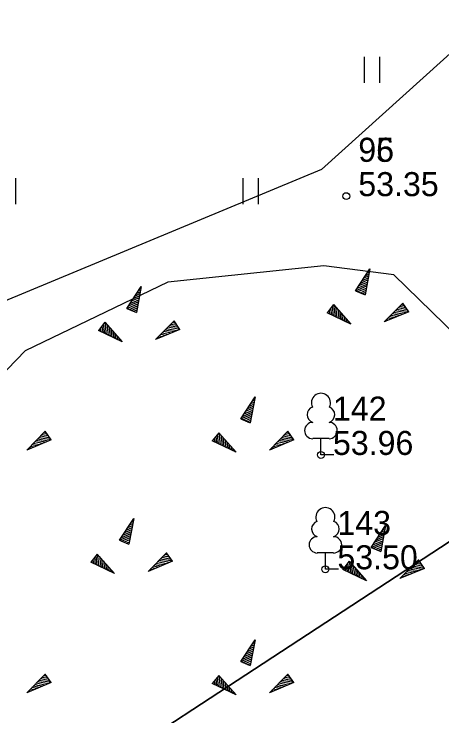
# Model space of a CAD drawing. Extents: x 538599 to 541973, y 6559689 to 6564516.
# Drawn here: x 540570.55 to 540583.02, y 6561313.83 to 6561334.28 of the extents above; entities that cross this region are included whole.
import ezdxf

# ---------------------------------------------------------------- set-up
doc = ezdxf.new("R2010")
doc.units = 0
for name, color, linetype in [('HALJASTUS', 7, 'Continuous'), ('KORGUS-EH2000', 7, 'Continuous'), ('MOOTKORG-EH2000', 7, 'Continuous'), ('MOOTMPUNKT', 7, 'Continuous'), ('MOOTNR', 7, 'Continuous'), ('MOOTPIIR', 7, 'Continuous'), ('PIIR', 7, 'Continuous'), ('PUU', 7, 'Continuous'), ('RELJEEF', 7, 'Continuous')]:
    doc.layers.add(name, color=color, linetype=linetype)

msp = doc.modelspace()

# ---------------------------------------------------------------- linework, layer by layer
at = {"layer": 'HALJASTUS'}
for p, q in [((540580.747, 6561333.033), (540580.747, 6561332.272)), ((540581.202, 6561333.033), (540581.202, 6561332.272)), ((540570.596, 6561329.498), (540570.596, 6561328.737)), ((540577.212, 6561329.498), (540577.212, 6561328.737)), ((540577.667, 6561329.498), (540577.667, 6561328.737))]:
    msp.add_line(p, q, dxfattribs=at)
at = {"layer": 'KORGUS-EH2000'}
msp.add_circle((540580.231, 6561328.973), 0.1, dxfattribs=at)
at = {"layer": 'MOOTMPUNKT'}
for centre in [(540580.231, 6561328.973), (540579.492, 6561321.433), (540579.622, 6561318.102)]:
    msp.add_circle(centre, 0.1, dxfattribs=at)
at = {"layer": 'MOOTPIIR'}
msp.add_lwpolyline([(540611.814, 6561347.628), (540600.551, 6561344.045), (540588.991, 6561338.307), (540579.507, 6561329.749), (540567.369, 6561324.711), (540557.296, 6561315.504), (540537.549, 6561303.29), (540525.23, 6561316.048), (540500.22, 6561345.282), (540476.488, 6561371.995), (540449.028, 6561405.277), (540428.792, 6561428.292), (540413.022, 6561448.218), (540405.096, 6561459.889), (540393.809, 6561473.145)], dxfattribs=at)
at = {"layer": 'PIIR'}
for points in [[(540501.31, 6561330.86), (540569.6, 6561385.93), (540606.26, 6561333.96), (540535.92, 6561287.97)], [(540535.92, 6561287.97), (540606.26, 6561333.96), (540640.63, 6561283.66), (540573.77, 6561238.75)]]:
    msp.add_lwpolyline(points, close=True, dxfattribs=at)
at = {"layer": 'PUU'}
for p, q in [((540579.732, 6561321.908), (540579.252, 6561321.908)), ((540579.492, 6561321.433), (540579.492, 6561321.908)), ((540579.872, 6561321.433), (540579.492, 6561321.433)), ((540579.862, 6561318.577), (540579.382, 6561318.577)), ((540579.622, 6561318.102), (540579.622, 6561318.577)), ((540580.002, 6561318.102), (540579.622, 6561318.102))]:
    msp.add_line(p, q, dxfattribs=at)
for centre, radius, start, end in [((540579.492, 6561322.953), 0.277, 332.5799, 207.4201), ((540579.322, 6561322.606), 0.233, 109.0217, 253.1415), ((540579.662, 6561322.606), 0.233, 286.8508, 70.9859), ((540579.255, 6561322.145), 0.238, 90.0016, 269.3953), ((540579.729, 6561322.145), 0.238, 270.6047, 89.9984), ((540579.622, 6561319.622), 0.277, 332.5799, 207.4201), ((540579.452, 6561319.275), 0.233, 109.0217, 253.1415), ((540579.792, 6561319.275), 0.233, 286.8508, 70.9859), ((540579.385, 6561318.814), 0.238, 90.0016, 269.3953), ((540579.859, 6561318.814), 0.238, 270.6047, 89.9984)]:
    msp.add_arc(centre, radius, start, end, dxfattribs=at)
at = {"layer": 'RELJEEF'}
for p, q in [((540580.501, 6561326.216), (540580.921, 6561326.856)), ((540580.921, 6561326.856), (540580.781, 6561326.101)), ((540580.896, 6561326.816), (540580.916, 6561326.826)), ((540580.701, 6561326.516), (540580.871, 6561326.591)), ((540580.751, 6561326.591), (540580.881, 6561326.651)), ((540580.796, 6561326.666), (540580.896, 6561326.706)), ((540580.846, 6561326.741), (540580.906, 6561326.766)), ((540580.551, 6561326.291), (540580.836, 6561326.411)), ((540580.601, 6561326.366), (540580.851, 6561326.471)), ((540580.651, 6561326.441), (540580.776, 6561326.496)), ((540580.776, 6561326.496), (540580.861, 6561326.531)), ((540573.835, 6561325.698), (540574.255, 6561326.338)), ((540574.255, 6561326.338), (540574.115, 6561325.583)), ((540574.13, 6561326.148), (540574.23, 6561326.188)), ((540574.18, 6561326.223), (540574.24, 6561326.248)), ((540574.23, 6561326.298), (540574.25, 6561326.308)), ((540580.501, 6561326.216), (540580.826, 6561326.356)), ((540580.501, 6561326.216), (540580.781, 6561326.101)), ((540580.566, 6561326.191), (540580.816, 6561326.296)), ((540580.631, 6561326.161), (540580.806, 6561326.236)), ((540580.701, 6561326.136), (540580.796, 6561326.176)), ((540573.935, 6561325.848), (540574.185, 6561325.953)), ((540573.985, 6561325.923), (540574.11, 6561325.978)), ((540574.035, 6561325.998), (540574.205, 6561326.073)), ((540574.085, 6561326.073), (540574.215, 6561326.133)), ((540574.11, 6561325.978), (540574.195, 6561326.013)), ((540580.766, 6561326.111), (540580.781, 6561326.116)), ((540573.835, 6561325.698), (540574.16, 6561325.838)), ((540573.885, 6561325.773), (540574.17, 6561325.893)), ((540573.9, 6561325.673), (540574.15, 6561325.778)), ((540579.86, 6561325.815), (540579.675, 6561325.575)), ((540579.815, 6561325.76), (540579.85, 6561325.49)), ((540579.86, 6561325.815), (540580.365, 6561325.245)), ((540579.86, 6561325.815), (540579.905, 6561325.465)), ((540579.92, 6561325.75), (540579.96, 6561325.44)), ((540581.339, 6561325.31), (540581.879, 6561325.855)), ((540581.969, 6561325.72), (540581.784, 6561325.755)), ((540581.929, 6561325.78), (540581.829, 6561325.8)), ((540581.889, 6561325.84), (540581.869, 6561325.84)), ((540582.049, 6561325.605), (540581.879, 6561325.855)), ((540573.835, 6561325.698), (540574.115, 6561325.583)), ((540573.965, 6561325.643), (540574.14, 6561325.718)), ((540574.035, 6561325.618), (540574.13, 6561325.658)), ((540574.1, 6561325.593), (540574.115, 6561325.598)), ((540580.365, 6561325.245), (540579.675, 6561325.575)), ((540579.685, 6561325.59), (540579.69, 6561325.57)), ((540579.73, 6561325.645), (540579.745, 6561325.545)), ((540579.775, 6561325.705), (540579.8, 6561325.52)), ((540579.98, 6561325.68), (540580.015, 6561325.415)), ((540580.04, 6561325.615), (540580.055, 6561325.475)), ((540580.095, 6561325.545), (540580.125, 6561325.36)), ((540582.049, 6561325.605), (540581.339, 6561325.31)), ((540581.664, 6561325.525), (540581.574, 6561325.545)), ((540581.879, 6561325.535), (540581.614, 6561325.585)), ((540581.964, 6561325.57), (540581.659, 6561325.63)), ((540582.049, 6561325.605), (540581.699, 6561325.67)), ((540582.009, 6561325.66), (540581.744, 6561325.715)), ((540574.672, 6561324.792), (540575.212, 6561325.337)), ((540575.382, 6561325.087), (540575.212, 6561325.337)), ((540580.055, 6561325.475), (540580.07, 6561325.385)), ((540580.155, 6561325.48), (540580.175, 6561325.335)), ((540580.215, 6561325.41), (540580.23, 6561325.31)), ((540580.275, 6561325.345), (540580.285, 6561325.28)), ((540581.464, 6561325.36), (540581.404, 6561325.375)), ((540581.549, 6561325.395), (540581.444, 6561325.415)), ((540581.629, 6561325.43), (540581.489, 6561325.46)), ((540581.714, 6561325.465), (540581.529, 6561325.5)), ((540581.799, 6561325.5), (540581.664, 6561325.525)), ((540573.193, 6561325.297), (540573.008, 6561325.057)), ((540573.108, 6561325.187), (540573.133, 6561325.002)), ((540573.148, 6561325.242), (540573.183, 6561324.972)), ((540573.193, 6561325.297), (540573.698, 6561324.727)), ((540573.193, 6561325.297), (540573.238, 6561324.947)), ((540573.253, 6561325.232), (540573.293, 6561324.922)), ((540573.313, 6561325.162), (540573.348, 6561324.897)), ((540575.382, 6561325.087), (540575.032, 6561325.152)), ((540575.342, 6561325.142), (540575.077, 6561325.197)), ((540575.302, 6561325.202), (540575.117, 6561325.237)), ((540575.262, 6561325.262), (540575.162, 6561325.282)), ((540575.222, 6561325.322), (540575.202, 6561325.322)), ((540580.335, 6561325.275), (540580.34, 6561325.255)), ((540581.379, 6561325.325), (540581.364, 6561325.33)), ((540573.698, 6561324.727), (540573.008, 6561325.057)), ((540573.018, 6561325.072), (540573.023, 6561325.052)), ((540573.063, 6561325.127), (540573.078, 6561325.027)), ((540573.373, 6561325.097), (540573.388, 6561324.957)), ((540573.388, 6561324.957), (540573.403, 6561324.867)), ((540573.428, 6561325.027), (540573.458, 6561324.842)), ((540573.488, 6561324.962), (540573.508, 6561324.817)), ((540575.382, 6561325.087), (540574.672, 6561324.792)), ((540574.962, 6561324.912), (540574.822, 6561324.942)), ((540575.047, 6561324.947), (540574.862, 6561324.982)), ((540574.997, 6561325.007), (540574.907, 6561325.027)), ((540575.212, 6561325.017), (540574.947, 6561325.067)), ((540575.297, 6561325.052), (540574.992, 6561325.112)), ((540575.132, 6561324.982), (540574.997, 6561325.007)), ((540573.548, 6561324.892), (540573.563, 6561324.792)), ((540573.608, 6561324.827), (540573.618, 6561324.762)), ((540573.668, 6561324.757), (540573.673, 6561324.737)), ((540574.712, 6561324.807), (540574.697, 6561324.812)), ((540574.797, 6561324.842), (540574.737, 6561324.857)), ((540574.882, 6561324.877), (540574.777, 6561324.897)), ((540577.153, 6561322.482), (540577.573, 6561323.122)), ((540577.573, 6561323.122), (540577.433, 6561322.367)), ((540577.548, 6561323.082), (540577.568, 6561323.092)), ((540577.403, 6561322.857), (540577.533, 6561322.917)), ((540577.448, 6561322.932), (540577.548, 6561322.972)), ((540577.498, 6561323.007), (540577.558, 6561323.032)), ((540577.203, 6561322.557), (540577.488, 6561322.677)), ((540577.253, 6561322.632), (540577.503, 6561322.737)), ((540577.303, 6561322.707), (540577.428, 6561322.762)), ((540577.353, 6561322.782), (540577.523, 6561322.857)), ((540577.428, 6561322.762), (540577.513, 6561322.797)), ((540577.153, 6561322.482), (540577.478, 6561322.622)), ((540577.153, 6561322.482), (540577.433, 6561322.367)), ((540577.218, 6561322.457), (540577.468, 6561322.562)), ((540577.283, 6561322.427), (540577.458, 6561322.502)), ((540577.353, 6561322.402), (540577.448, 6561322.442)), ((540577.418, 6561322.377), (540577.433, 6561322.382)), ((540570.92, 6561321.576), (540571.46, 6561322.121)), ((540571.51, 6561322.046), (540571.41, 6561322.066)), ((540571.47, 6561322.106), (540571.45, 6561322.106)), ((540571.63, 6561321.871), (540571.46, 6561322.121)), ((540576.512, 6561322.081), (540576.327, 6561321.841)), ((540576.512, 6561322.081), (540577.017, 6561321.511)), ((540576.512, 6561322.081), (540576.557, 6561321.731)), ((540577.991, 6561321.576), (540578.531, 6561322.121)), ((540578.581, 6561322.046), (540578.481, 6561322.066)), ((540578.541, 6561322.106), (540578.521, 6561322.106)), ((540578.701, 6561321.871), (540578.531, 6561322.121)), ((540571.63, 6561321.871), (540570.92, 6561321.576)), ((540571.545, 6561321.836), (540571.24, 6561321.896)), ((540571.63, 6561321.871), (540571.28, 6561321.936)), ((540571.59, 6561321.926), (540571.325, 6561321.981)), ((540571.55, 6561321.986), (540571.365, 6561322.021)), ((540576.382, 6561321.911), (540576.397, 6561321.811)), ((540576.427, 6561321.971), (540576.452, 6561321.786)), ((540576.467, 6561322.026), (540576.502, 6561321.756)), ((540576.572, 6561322.016), (540576.612, 6561321.706)), ((540576.632, 6561321.946), (540576.667, 6561321.681)), ((540576.692, 6561321.881), (540576.707, 6561321.741)), ((540578.701, 6561321.871), (540577.991, 6561321.576)), ((540578.616, 6561321.836), (540578.311, 6561321.896)), ((540578.701, 6561321.871), (540578.351, 6561321.936)), ((540578.661, 6561321.926), (540578.396, 6561321.981)), ((540578.621, 6561321.986), (540578.436, 6561322.021)), ((540571.13, 6561321.661), (540571.025, 6561321.681)), ((540571.21, 6561321.696), (540571.07, 6561321.726)), ((540571.295, 6561321.731), (540571.11, 6561321.766)), ((540571.245, 6561321.791), (540571.155, 6561321.811)), ((540571.46, 6561321.801), (540571.195, 6561321.851)), ((540571.38, 6561321.766), (540571.245, 6561321.791)), ((540577.017, 6561321.511), (540576.327, 6561321.841)), ((540576.337, 6561321.856), (540576.342, 6561321.836)), ((540576.707, 6561321.741), (540576.722, 6561321.651)), ((540576.747, 6561321.811), (540576.777, 6561321.626)), ((540576.807, 6561321.746), (540576.827, 6561321.601)), ((540576.867, 6561321.676), (540576.882, 6561321.576)), ((540578.201, 6561321.661), (540578.096, 6561321.681)), ((540578.281, 6561321.696), (540578.141, 6561321.726)), ((540578.366, 6561321.731), (540578.181, 6561321.766)), ((540578.316, 6561321.791), (540578.226, 6561321.811)), ((540578.531, 6561321.801), (540578.266, 6561321.851)), ((540578.451, 6561321.766), (540578.316, 6561321.791)), ((540570.96, 6561321.591), (540570.945, 6561321.596)), ((540571.045, 6561321.626), (540570.985, 6561321.641)), ((540576.927, 6561321.611), (540576.937, 6561321.546)), ((540576.987, 6561321.541), (540576.992, 6561321.521)), ((540578.031, 6561321.591), (540578.016, 6561321.596)), ((540578.116, 6561321.626), (540578.056, 6561321.641)), ((540573.618, 6561318.946), (540574.038, 6561319.586)), ((540574.038, 6561319.586), (540573.898, 6561318.831)), ((540573.913, 6561319.396), (540574.013, 6561319.436)), ((540573.963, 6561319.471), (540574.023, 6561319.496)), ((540574.013, 6561319.546), (540574.033, 6561319.556)), ((540573.718, 6561319.096), (540573.968, 6561319.201)), ((540573.768, 6561319.171), (540573.893, 6561319.226)), ((540573.818, 6561319.246), (540573.988, 6561319.321)), ((540573.868, 6561319.321), (540573.998, 6561319.381)), ((540573.893, 6561319.226), (540573.978, 6561319.261)), ((540580.957, 6561318.739), (540581.377, 6561319.379)), ((540581.377, 6561319.379), (540581.237, 6561318.624)), ((540581.252, 6561319.189), (540581.352, 6561319.229)), ((540581.302, 6561319.264), (540581.362, 6561319.289)), ((540581.352, 6561319.339), (540581.372, 6561319.349)), ((540573.618, 6561318.946), (540573.943, 6561319.086)), ((540573.668, 6561319.021), (540573.953, 6561319.141)), ((540573.683, 6561318.921), (540573.933, 6561319.026)), ((540581.107, 6561318.964), (540581.232, 6561319.019)), ((540581.157, 6561319.039), (540581.327, 6561319.114)), ((540581.207, 6561319.114), (540581.337, 6561319.174)), ((540581.232, 6561319.019), (540581.317, 6561319.054)), ((540573.618, 6561318.946), (540573.898, 6561318.831)), ((540573.748, 6561318.891), (540573.923, 6561318.966)), ((540573.818, 6561318.866), (540573.913, 6561318.906)), ((540573.883, 6561318.841), (540573.898, 6561318.846)), ((540580.957, 6561318.739), (540581.282, 6561318.879)), ((540581.007, 6561318.814), (540581.292, 6561318.934)), ((540581.022, 6561318.714), (540581.272, 6561318.819)), ((540581.057, 6561318.889), (540581.307, 6561318.994)), ((540580.957, 6561318.739), (540581.237, 6561318.624)), ((540581.087, 6561318.684), (540581.262, 6561318.759)), ((540581.157, 6561318.659), (540581.252, 6561318.699)), ((540581.222, 6561318.634), (540581.237, 6561318.639)), ((540572.976, 6561318.545), (540572.791, 6561318.305)), ((540572.891, 6561318.435), (540572.916, 6561318.25)), ((540572.931, 6561318.49), (540572.966, 6561318.22)), ((540572.976, 6561318.545), (540573.481, 6561317.975)), ((540572.976, 6561318.545), (540573.021, 6561318.195)), ((540573.036, 6561318.48), (540573.076, 6561318.17)), ((540573.096, 6561318.41), (540573.131, 6561318.145)), ((540574.455, 6561318.04), (540574.995, 6561318.585)), ((540575.165, 6561318.335), (540574.815, 6561318.4)), ((540575.125, 6561318.39), (540574.86, 6561318.445)), ((540575.085, 6561318.45), (540574.9, 6561318.485)), ((540575.045, 6561318.51), (540574.945, 6561318.53)), ((540575.005, 6561318.57), (540574.985, 6561318.57)), ((540575.165, 6561318.335), (540574.995, 6561318.585)), ((540573.481, 6561317.975), (540572.791, 6561318.305)), ((540572.801, 6561318.32), (540572.806, 6561318.3)), ((540572.846, 6561318.375), (540572.861, 6561318.275)), ((540573.156, 6561318.345), (540573.171, 6561318.205)), ((540573.171, 6561318.205), (540573.186, 6561318.115)), ((540573.211, 6561318.275), (540573.241, 6561318.09)), ((540573.271, 6561318.21), (540573.291, 6561318.065)), ((540575.165, 6561318.335), (540574.455, 6561318.04)), ((540574.745, 6561318.16), (540574.605, 6561318.19)), ((540574.83, 6561318.195), (540574.645, 6561318.23)), ((540574.78, 6561318.255), (540574.69, 6561318.275)), ((540574.995, 6561318.265), (540574.73, 6561318.315)), ((540575.08, 6561318.3), (540574.775, 6561318.36)), ((540574.915, 6561318.23), (540574.78, 6561318.255)), ((540580.315, 6561318.338), (540580.13, 6561318.098)), ((540580.23, 6561318.228), (540580.255, 6561318.043)), ((540580.27, 6561318.283), (540580.305, 6561318.013)), ((540580.315, 6561318.338), (540580.82, 6561317.768)), ((540580.315, 6561318.338), (540580.36, 6561317.988)), ((540580.375, 6561318.273), (540580.415, 6561317.963)), ((540580.435, 6561318.203), (540580.47, 6561317.938)), ((540581.795, 6561317.833), (540582.335, 6561318.378)), ((540582.505, 6561318.128), (540582.155, 6561318.193)), ((540582.465, 6561318.183), (540582.2, 6561318.238)), ((540582.425, 6561318.243), (540582.24, 6561318.278)), ((540582.385, 6561318.303), (540582.285, 6561318.323)), ((540582.345, 6561318.363), (540582.325, 6561318.363)), ((540582.505, 6561318.128), (540582.335, 6561318.378)), ((540573.331, 6561318.14), (540573.346, 6561318.04)), ((540573.391, 6561318.075), (540573.401, 6561318.01)), ((540573.451, 6561318.005), (540573.456, 6561317.985)), ((540574.495, 6561318.055), (540574.48, 6561318.06)), ((540574.58, 6561318.09), (540574.52, 6561318.105)), ((540574.665, 6561318.125), (540574.56, 6561318.145)), ((540580.82, 6561317.768), (540580.13, 6561318.098)), ((540580.14, 6561318.113), (540580.145, 6561318.093)), ((540580.185, 6561318.168), (540580.2, 6561318.068)), ((540580.495, 6561318.138), (540580.51, 6561317.998)), ((540580.51, 6561317.998), (540580.525, 6561317.908)), ((540580.55, 6561318.068), (540580.58, 6561317.883)), ((540580.61, 6561318.003), (540580.63, 6561317.858)), ((540582.505, 6561318.128), (540581.795, 6561317.833)), ((540582.085, 6561317.953), (540581.945, 6561317.983)), ((540582.17, 6561317.988), (540581.985, 6561318.023)), ((540582.12, 6561318.048), (540582.03, 6561318.068)), ((540582.335, 6561318.058), (540582.07, 6561318.108)), ((540582.42, 6561318.093), (540582.115, 6561318.153)), ((540582.255, 6561318.023), (540582.12, 6561318.048)), ((540580.67, 6561317.933), (540580.685, 6561317.833)), ((540580.73, 6561317.868), (540580.74, 6561317.803)), ((540580.79, 6561317.798), (540580.795, 6561317.778)), ((540581.835, 6561317.848), (540581.82, 6561317.853)), ((540581.92, 6561317.883), (540581.86, 6561317.898)), ((540582.005, 6561317.918), (540581.9, 6561317.938)), ((540577.153, 6561315.411), (540577.573, 6561316.051)), ((540577.573, 6561316.051), (540577.433, 6561315.296)), ((540577.498, 6561315.936), (540577.558, 6561315.961)), ((540577.548, 6561316.011), (540577.568, 6561316.021)), ((540577.353, 6561315.711), (540577.523, 6561315.786)), ((540577.403, 6561315.786), (540577.533, 6561315.846)), ((540577.428, 6561315.691), (540577.513, 6561315.726)), ((540577.448, 6561315.861), (540577.548, 6561315.901)), ((540577.153, 6561315.411), (540577.478, 6561315.551)), ((540577.203, 6561315.486), (540577.488, 6561315.606)), ((540577.253, 6561315.561), (540577.503, 6561315.666)), ((540577.303, 6561315.636), (540577.428, 6561315.691)), ((540577.153, 6561315.411), (540577.433, 6561315.296)), ((540577.218, 6561315.386), (540577.468, 6561315.491)), ((540577.283, 6561315.356), (540577.458, 6561315.431)), ((540577.353, 6561315.331), (540577.448, 6561315.371)), ((540577.418, 6561315.306), (540577.433, 6561315.311)), ((540570.92, 6561314.505), (540571.46, 6561315.05)), ((540571.59, 6561314.855), (540571.325, 6561314.91)), ((540571.55, 6561314.915), (540571.365, 6561314.95)), ((540571.51, 6561314.975), (540571.41, 6561314.995)), ((540571.47, 6561315.035), (540571.45, 6561315.035)), ((540571.63, 6561314.8), (540571.46, 6561315.05)), ((540576.512, 6561315.01), (540576.327, 6561314.77)), ((540576.467, 6561314.955), (540576.502, 6561314.685)), ((540576.512, 6561315.01), (540577.017, 6561314.44)), ((540576.512, 6561315.01), (540576.557, 6561314.66)), ((540576.572, 6561314.945), (540576.612, 6561314.635)), ((540577.991, 6561314.505), (540578.531, 6561315.05)), ((540578.661, 6561314.855), (540578.396, 6561314.91)), ((540578.621, 6561314.915), (540578.436, 6561314.95)), ((540578.581, 6561314.975), (540578.481, 6561314.995)), ((540578.541, 6561315.035), (540578.521, 6561315.035)), ((540578.701, 6561314.8), (540578.531, 6561315.05)), ((540571.63, 6561314.8), (540570.92, 6561314.505)), ((540571.245, 6561314.72), (540571.155, 6561314.74)), ((540571.46, 6561314.73), (540571.195, 6561314.78)), ((540571.545, 6561314.765), (540571.24, 6561314.825)), ((540571.38, 6561314.695), (540571.245, 6561314.72)), ((540571.63, 6561314.8), (540571.28, 6561314.865)), ((540577.017, 6561314.44), (540576.327, 6561314.77)), ((540576.337, 6561314.785), (540576.342, 6561314.765)), ((540576.382, 6561314.84), (540576.397, 6561314.74)), ((540576.427, 6561314.9), (540576.452, 6561314.715)), ((540576.632, 6561314.875), (540576.667, 6561314.61)), ((540576.692, 6561314.81), (540576.707, 6561314.67)), ((540576.747, 6561314.74), (540576.777, 6561314.555)), ((540578.701, 6561314.8), (540577.991, 6561314.505)), ((540578.316, 6561314.72), (540578.226, 6561314.74)), ((540578.531, 6561314.73), (540578.266, 6561314.78)), ((540578.616, 6561314.765), (540578.311, 6561314.825)), ((540578.451, 6561314.695), (540578.316, 6561314.72)), ((540578.701, 6561314.8), (540578.351, 6561314.865)), ((540570.96, 6561314.52), (540570.945, 6561314.525)), ((540571.045, 6561314.555), (540570.985, 6561314.57)), ((540571.13, 6561314.59), (540571.025, 6561314.61)), ((540571.21, 6561314.625), (540571.07, 6561314.655)), ((540571.295, 6561314.66), (540571.11, 6561314.695)), ((540576.707, 6561314.67), (540576.722, 6561314.58)), ((540576.807, 6561314.675), (540576.827, 6561314.53)), ((540576.867, 6561314.605), (540576.882, 6561314.505)), ((540576.927, 6561314.54), (540576.937, 6561314.475)), ((540578.031, 6561314.52), (540578.016, 6561314.525)), ((540578.116, 6561314.555), (540578.056, 6561314.57)), ((540578.201, 6561314.59), (540578.096, 6561314.61)), ((540578.281, 6561314.625), (540578.141, 6561314.655)), ((540578.366, 6561314.66), (540578.181, 6561314.695)), ((540576.987, 6561314.47), (540576.992, 6561314.45))]:
    msp.add_line(p, q, dxfattribs=at)
msp.add_lwpolyline([(540589.422, 6561307.792), (540589.68, 6561309.123), (540589.163, 6561314.56), (540588.123, 6561318.281), (540586.874, 6561320.9), (540584.555, 6561323.82), (540581.615, 6561326.678), (540579.576, 6561326.947), (540575.031, 6561326.471), (540570.87, 6561324.462), (540568.551, 6561322.069), (540567.391, 6561319.222), (540568.551, 6561316.219), (540571.622, 6561311.338), (540573.345, 6561309.041), (540578.266, 6561303.19), (540579.463, 6561302.544), (540580.81, 6561302.787), (540585.578, 6561304.743), (540588.479, 6561306.571), (540589.422, 6561307.792)], dxfattribs=at)

# ---------------------------------------------------------------- texts
at = {"layer": 'KORGUS-EH2000'}
msp.add_text('53.35', height=0.7, dxfattribs=at).set_placement((540580.581, 6561328.973))
at = {"layer": 'MOOTKORG-EH2000'}
for s, p in [('53.35', (540580.581, 6561328.973)), ('53.96', (540579.842, 6561321.433)), ('53.50', (540579.972, 6561318.102))]:
    msp.add_text(s, height=0.7, dxfattribs=at).set_placement(p)
at = {"layer": 'MOOTNR'}
for s, p in [('96', (540580.581, 6561329.975)), ('95', (540580.581, 6561329.973)), ('142', (540579.842, 6561322.433)), ('143', (540579.972, 6561319.102))]:
    msp.add_text(s, height=0.7, dxfattribs=at).set_placement(p)

doc.saveas('drawing.dxf')
